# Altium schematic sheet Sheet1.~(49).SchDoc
size A1; SheetNumber: 1; SheetTotal: 1
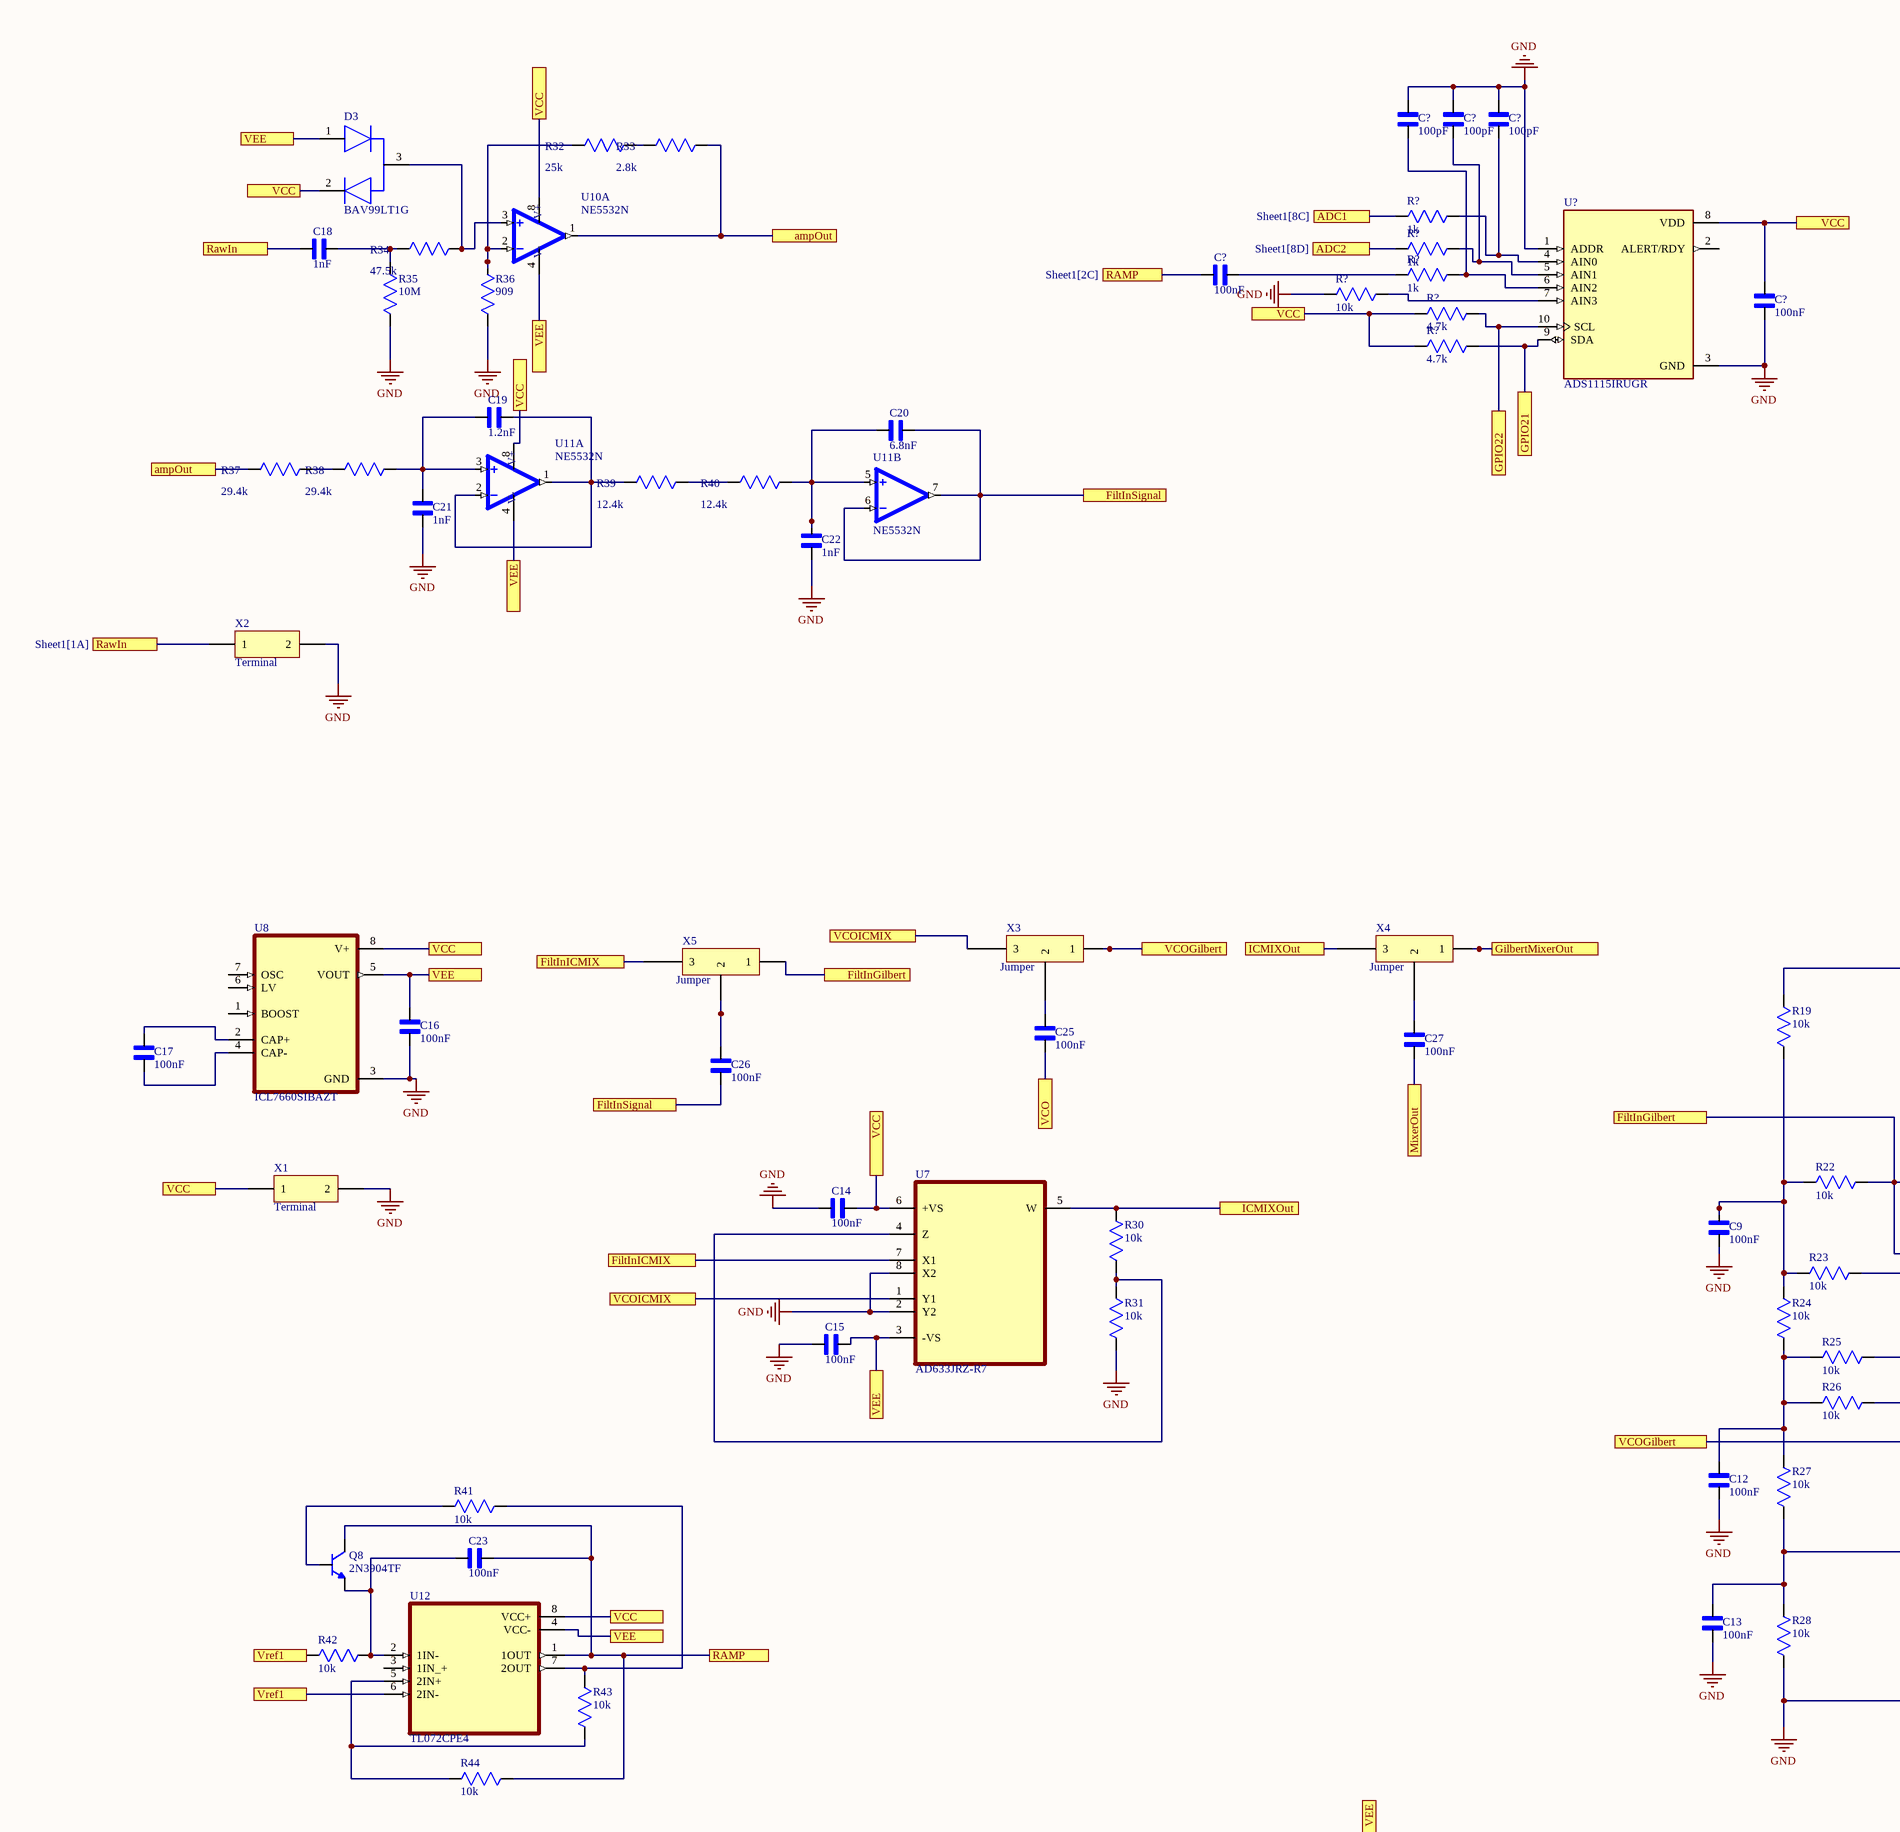
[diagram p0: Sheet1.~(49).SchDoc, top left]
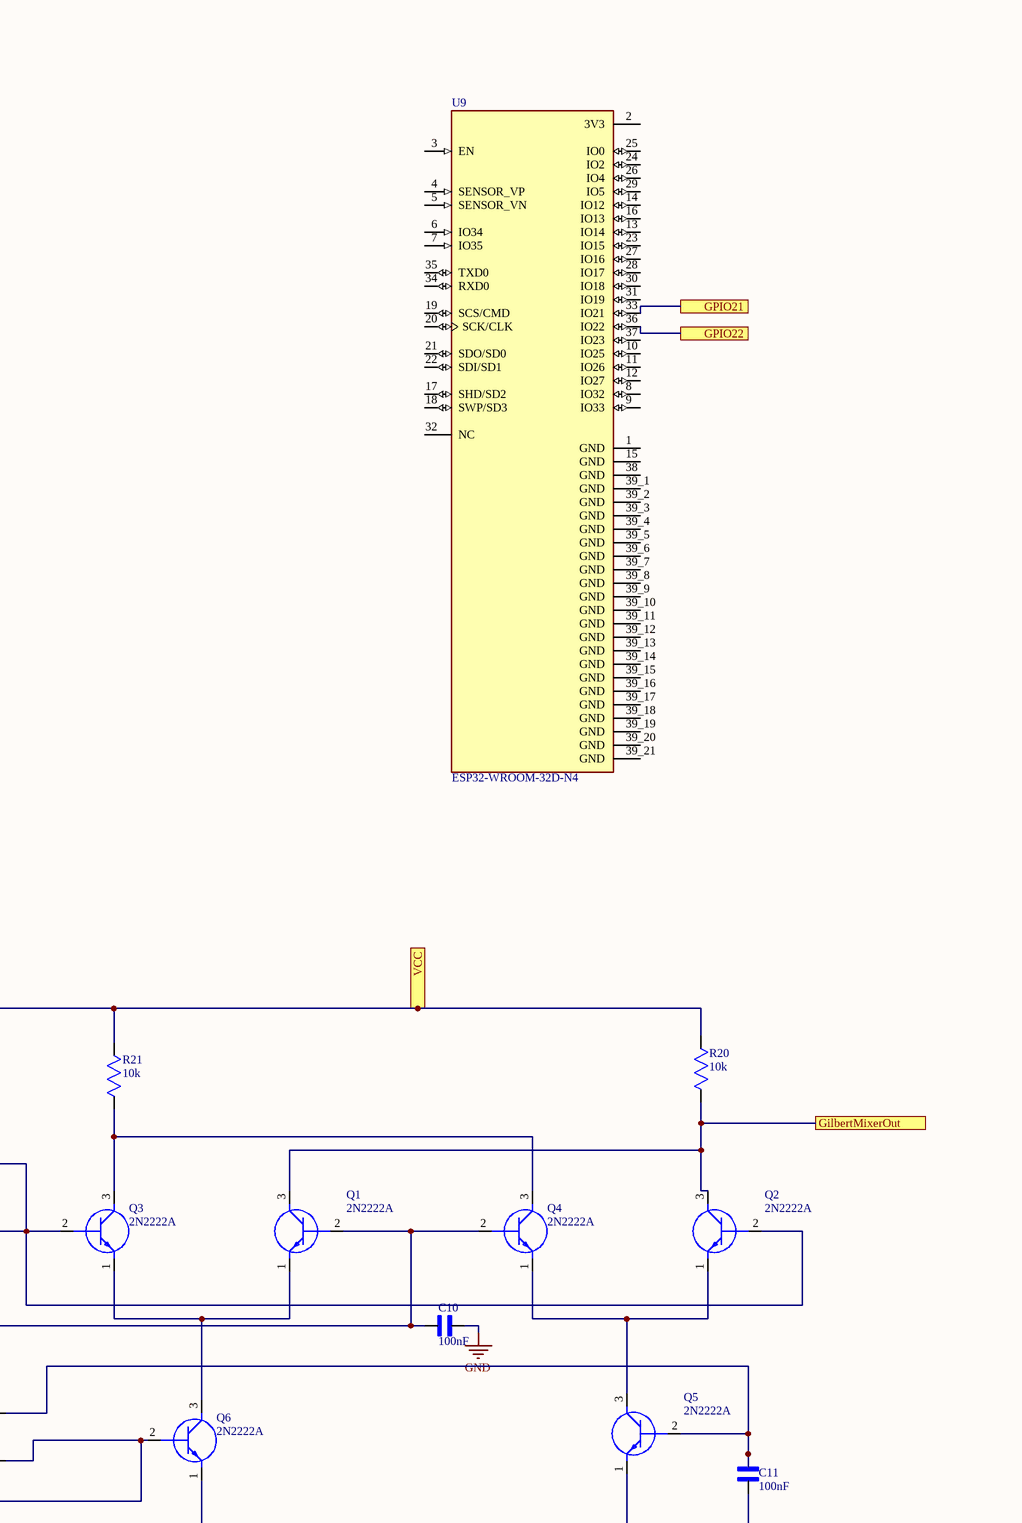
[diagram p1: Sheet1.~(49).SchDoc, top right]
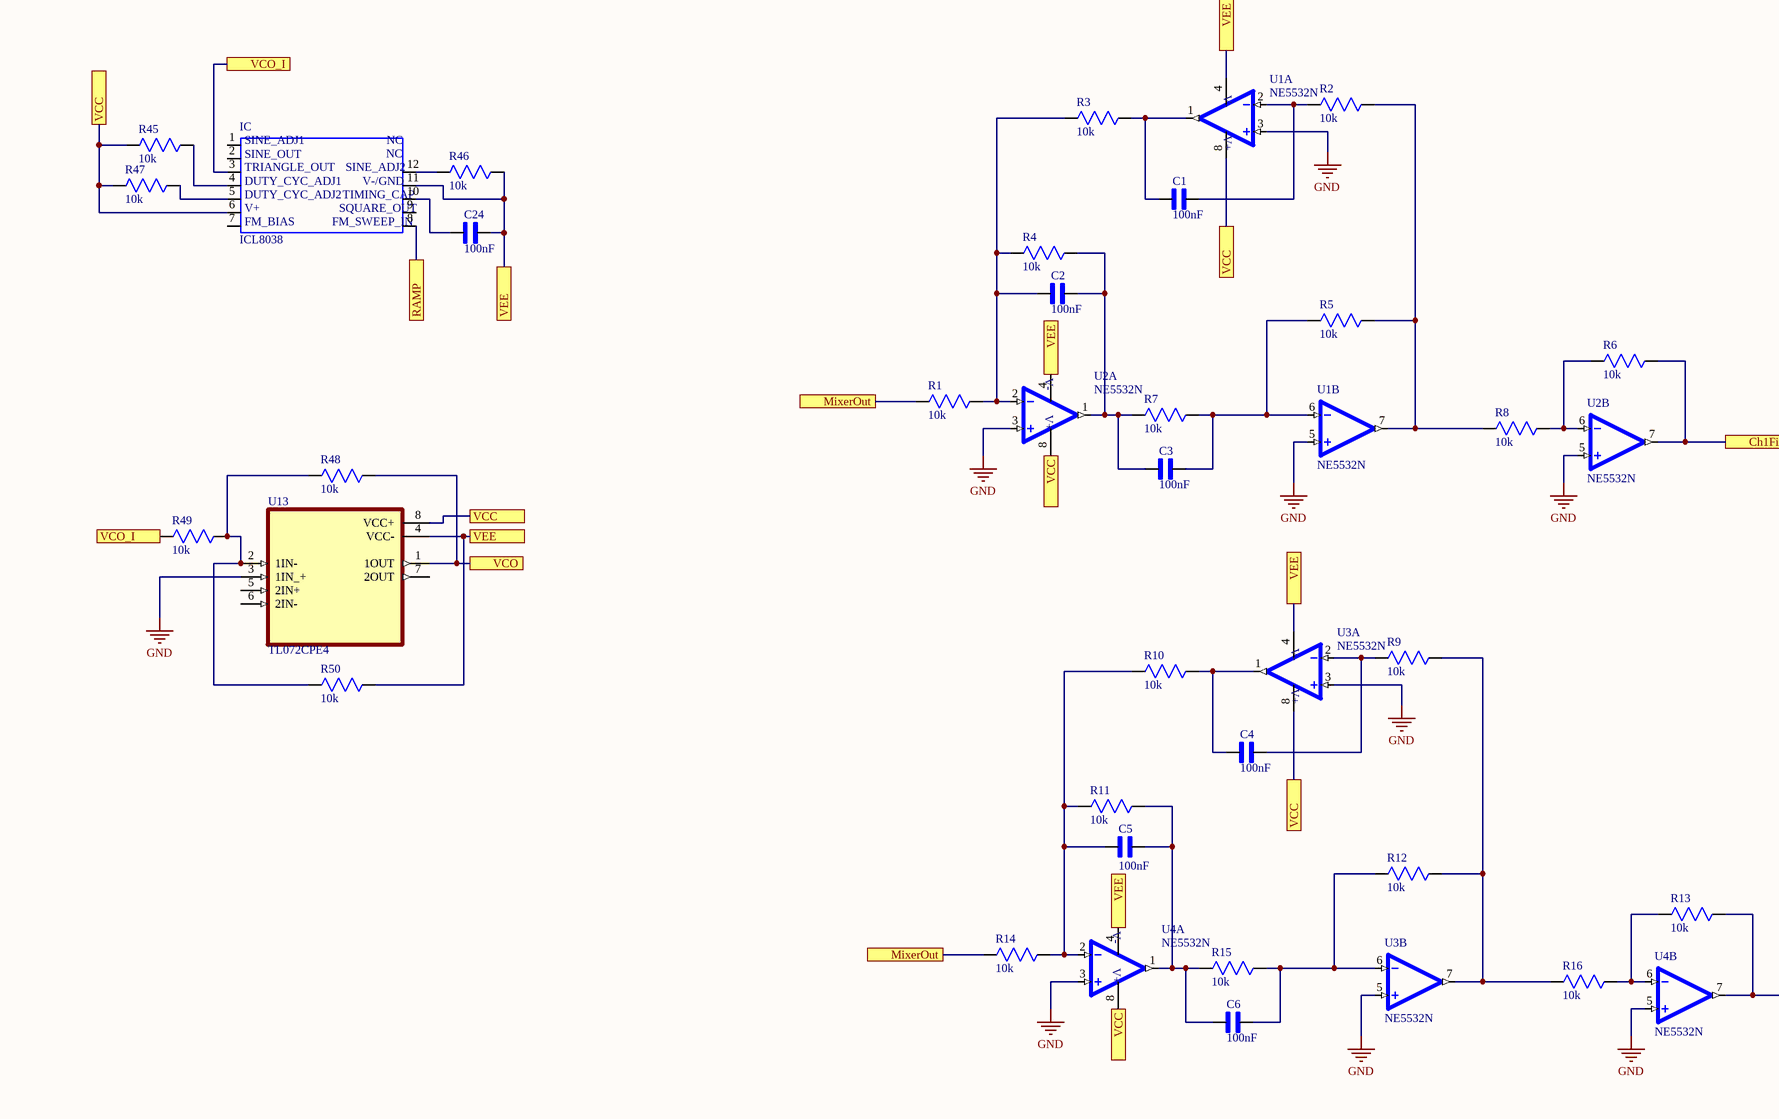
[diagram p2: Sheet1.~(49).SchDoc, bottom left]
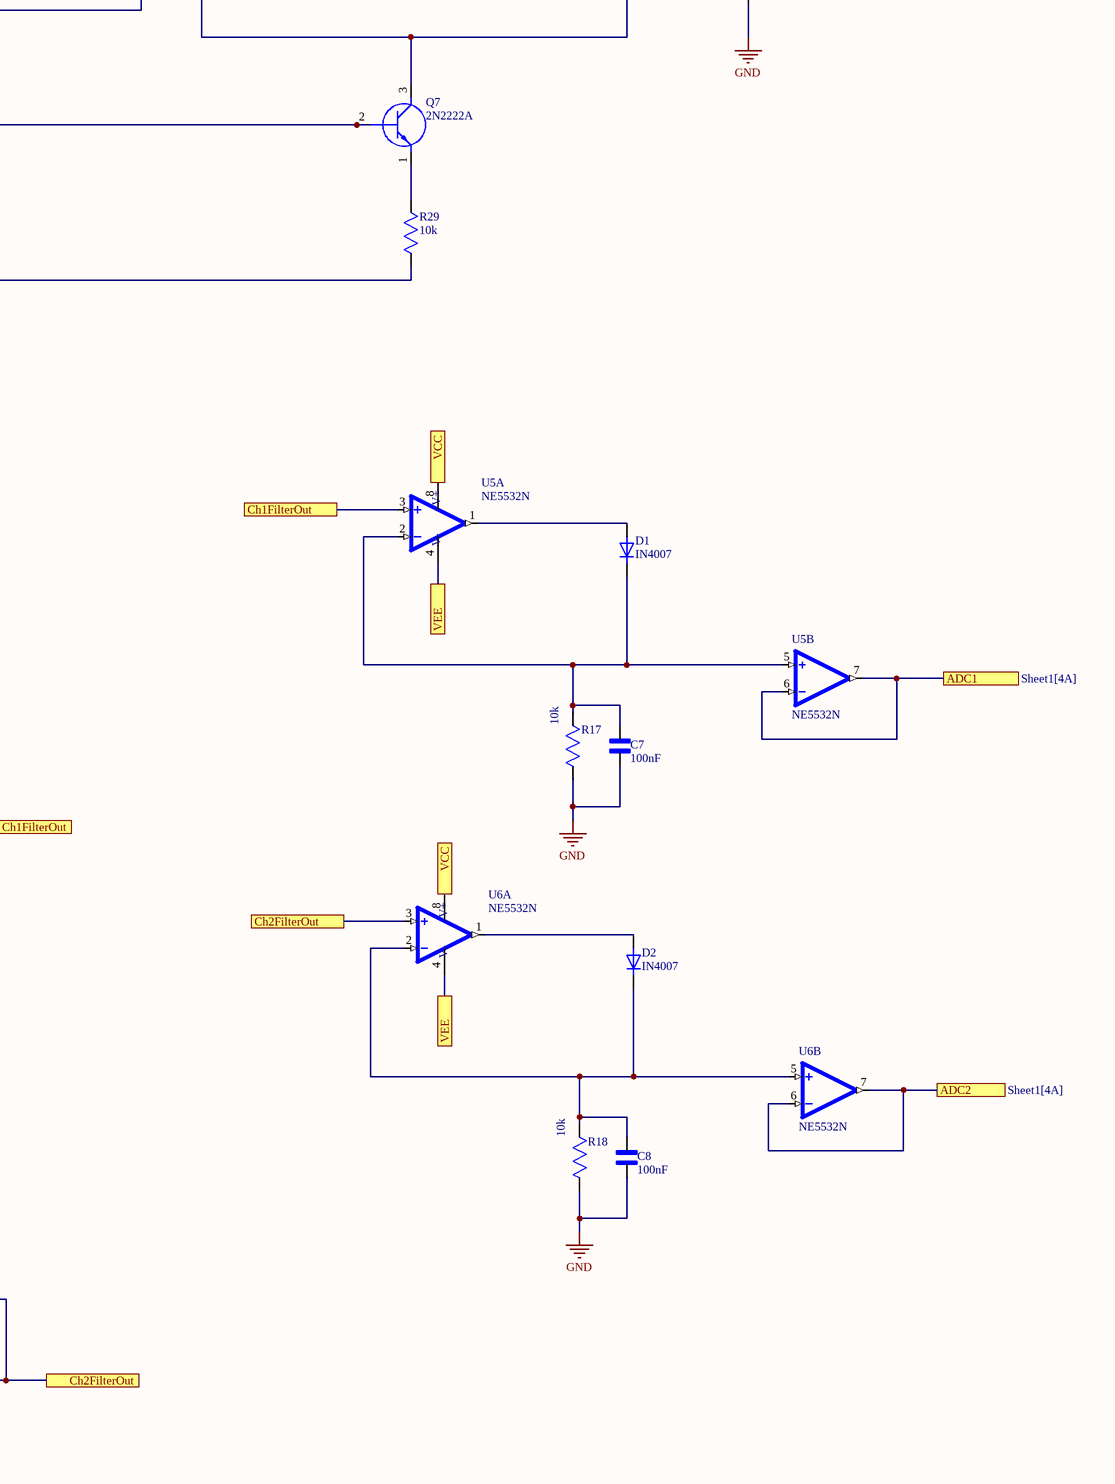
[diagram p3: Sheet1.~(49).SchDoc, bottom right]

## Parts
(Parts that share a designator on the sheet are numbered #1, #2 ... from top to bottom, then left to right.)
C1  100nF  [CAPC2012X95N]
C2  100nF  [CAPC2012X95N]
C3  100nF  [CAPC2012X95N]
C4  100nF  [CAPC2012X95N]
C5  100nF  [CAPC2012X95N]
C6  100nF  [CAPC2012X95N]
C7  100nF  [CAPC2012X95N]
C8  100nF  [CAPC2012X95N]
C9  100nF  [CAPC2012X95N]
C10  100nF  [CAPC2012X95N]
C11  100nF  [CAPC2012X95N]
C12  100nF  [CAPC2012X95N]
C13  100nF  [CAPC2012X95N]
C14  100nF  [CAPC2012X95N]
C15  100nF  [CAPC2012X95N]
C16  100nF  [CAPC2012X95N]
C17  100nF  [CAPC2012X95N]
C18  1nF  [CAPC2012X95N]
C19  1.2nF  [CAPC2012X95N]
C20  6.8nF  [CAPC2012X95N]
C21  1nF  [CAPC2012X95N]
C22  1nF  [CAPC2012X95N]
C23  100nF  [CAPC2012X95N]
C24  100nF  [CAPC2012X95N]
C25  100nF  [CAPC2012X95N]
C26  100nF  [CAPC2012X95N]
C27  100nF  [CAPC2012X95N]
C?#1  100pF  [CAPC2012X95N]
C?#2  100pF  [CAPC2012X95N]
C?#3  100pF  [CAPC2012X95N]
C?#4  100nF  [CAPC2012X95N]
C?#5  100nF  [CAPC2012X95N]
D1  IN4007  [DIOAD1070W78L470D235P]
D2  IN4007  [DIOAD1070W78L470D235P]
D3  BAV99LT1G  [FP-318-08-IPC_B]
IC  ICL8038  [ICL8038]
Q1  2N2222A  [2N2222A]
Q2  2N2222A  [2N2222A]
Q3  2N2222A  [2N2222A]
Q4  2N2222A  [2N2222A]
Q5  2N2222A  [2N2222A]
Q6  2N2222A  [2N2222A]
Q7  2N2222A  [2N2222A]
Q8  2N3904TF  [TO92254P520H877-3]
R1  10k  [RC0805N_YAG-M]
R2  10k  [RC0805N_YAG-M]
R3  10k  [RC0805N_YAG-M]
R4  10k  [RC0805N_YAG-M]
R5  10k  [RC0805N_YAG-M]
R6  10k  [RC0805N_YAG-M]
R7  10k  [RC0805N_YAG-M]
R8  10k  [RC0805N_YAG-M]
R9  10k  [RC0805N_YAG-M]
R10  10k  [RC0805N_YAG-M]
R11  10k  [RC0805N_YAG-M]
R12  10k  [RC0805N_YAG-M]
R13  10k  [RC0805N_YAG-M]
R14  10k  [RC0805N_YAG-M]
R15  10k  [RC0805N_YAG-M]
R16  10k  [RC0805N_YAG-M]
R17  10k  [RC0805N_YAG-M]
R18  10k  [RC0805N_YAG-M]
R19  10k  [RC0805N_YAG-M]
R20  10k  [RC0805N_YAG-M]
R21  10k  [RC0805N_YAG-M]
R22  10k  [RC0805N_YAG-M]
R23  10k  [RC0805N_YAG-M]
R24  10k  [RC0805N_YAG-M]
R25  10k  [RC0805N_YAG-M]
R26  10k  [RC0805N_YAG-M]
R27  10k  [RC0805N_YAG-M]
R28  10k  [RC0805N_YAG-M]
R29  10k  [RC0805N_YAG-M]
R30  10k  [RC0805N_YAG-M]
R31  10k  [RC0805N_YAG-M]
R32  25k  [RC0805N_YAG-M]
R33  2.8k  [RC0805N_YAG-M]
R34  47.5k  [RC0805N_YAG-M]
R35  10M  [RC0805N_YAG-M]
R36  909  [RC0805N_YAG-M]
R37  29.4k  [RC0805N_YAG-M]
R38  29.4k  [RC0805N_YAG-M]
R39  12.4k  [RC0805N_YAG-M]
R40  12.4k  [RC0805N_YAG-M]
R41  10k  [RC0805N_YAG-M]
R42  10k  [RC0805N_YAG-M]
R43  10k  [RC0805N_YAG-M]
R44  10k  [RC0805N_YAG-M]
R45  10k  [RC0805N_YAG-M]
R46  10k  [RC0805N_YAG-M]
R47  10k  [RC0805N_YAG-M]
R48  10k  [RC0805N_YAG-M]
R49  10k  [RC0805N_YAG-M]
R50  10k  [RC0805N_YAG-M]
R?#1  1k  [RC0805N_YAG-M]
R?#2  1k  [RC0805N_YAG-M]
R?#3  1k  [RC0805N_YAG-M]
R?#4  10k  [RC0805N_YAG-M]
R?#5  4.7k  [RC0805N_YAG-M]
R?#6  4.7k  [RC0805N_YAG-M]
U1  NE5532N  [DIP766W45P254L1016H533Q8]  (parts A,B of 2)
U2  NE5532N  [DIP766W45P254L1016H533Q8]  (parts A,B of 2)
U3  NE5532N  [DIP766W45P254L1016H533Q8]  (parts A,B of 2)
U4  NE5532N  [DIP766W45P254L1016H533Q8]  (parts A,B of 2)
U5  NE5532N  [DIP766W45P254L1016H533Q8]  (parts A,B of 2)
U6  NE5532N  [DIP766W45P254L1016H533Q8]  (parts A,B of 2)
U7  AD633JRZ-R7  [SOIC127P600X175-8N]
U8  ICL7660SIBAZT  [SOIC127P600X175-8N]
U9  ESP32-WROOM-32D-N4  [MODULE_ESP32-WROOM-32D-N4]
U10  NE5532N  [DIP766W45P254L1016H533Q8]  (part A of 2)
U11  NE5532N  [DIP766W45P254L1016H533Q8]  (parts A,B of 2)
U12  TL072CPE4  [DIP794W45P254L959H508Q8]
U13  TL072CPE4  [DIP794W45P254L959H508Q8]
U?  ADS1115IRUGR  [IC_ADS1115IRUGR]
X1  Terminal  [CON_TERMINAL_2POL]
X2  Terminal  [CON_TERMINAL_2POL]
X3  Jumper  [CON_JUMPER_3POL]
X4  Jumper  [CON_JUMPER_3POL]
X5  Jumper  [CON_JUMPER_3POL]

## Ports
ADC1 (see Sheet1[4A]), ADC1 (see Sheet1[8C]), ADC2 (see Sheet1[4A]), ADC2 (see Sheet1[8D]), ampOut (see Sheet1[1A]), ampOut (see Sheet1[3A]), Ch1FilterOut (see Sheet1[6D]), Ch1FilterOut (see Sheet1[7C]), Ch2FilterOut (see Sheet1[6D]), Ch2FilterOut (see Sheet1[7D]), FiltInGilbert (see Sheet1[3B]), FiltInGilbert (see Sheet1[5B]), FiltInICMIX (see Sheet1[2B]), FiltInSignal (see Sheet1[2B]), FiltInSignal (see Sheet1[4A]), GilbertMixerOut (see Sheet1[5B]), GilbertMixerOut (see Sheet1[8B]), GPIO21 (see Sheet1[5A]), GPIO21 (see Sheet1[8A]), GPIO22 (see Sheet1[5A]), GPIO22 (see Sheet1[8A]), ICMIXOut (see Sheet1[4B]), MixerOut (see Sheet1[3D]), MixerOut (see Sheet1[3D], Sheet1[4B]), RAMP (see Sheet1[2C]), RAMP (see Sheet1[2C], Sheet1[4A]), RawIn (see Sheet1[1A]), VCC (see Sheet1[1A], Sheet1[1B], Sheet1[1C], Sheet1[2A], Sheet1[2B], Sheet1[2C], Sheet1[2D], Sheet1[3B], Sheet1[4A], Sheet1[4C], Sheet1[4D], Sheet1[5D], Sheet1[6A], Sheet1[7B], Sheet1[7C]), VCC (see Sheet1[1A], Sheet1[1B], Sheet1[1C], Sheet1[2A], Sheet1[2B], Sheet1[2C], Sheet1[2D], Sheet1[3B], Sheet1[4A], Sheet1[4C], Sheet1[4D], Sheet1[5D], Sheet1[6A], Sheet1[7B], Sheet1[7C], Sheet1[7D]), VCC (see Sheet1[1A], Sheet1[1B], Sheet1[1C], Sheet1[2A], Sheet1[2B], Sheet1[2C], Sheet1[2D], Sheet1[3B], Sheet1[4A], Sheet1[4C], Sheet1[4D], Sheet1[5D], Sheet1[6A], Sheet1[7B], Sheet1[7D]), VCC (see Sheet1[1A], Sheet1[1B], Sheet1[1C], Sheet1[2A], Sheet1[2B], Sheet1[2C], Sheet1[2D], Sheet1[3B], Sheet1[4A], Sheet1[4C], Sheet1[4D], Sheet1[5D], Sheet1[6A], Sheet1[7C], Sheet1[7D]), VCC (see Sheet1[1A], Sheet1[1B], Sheet1[1C], Sheet1[2A], Sheet1[2B], Sheet1[2C], Sheet1[2D], Sheet1[3B], Sheet1[4A], Sheet1[4C], Sheet1[4D], Sheet1[5D], Sheet1[7B], Sheet1[7C], Sheet1[7D]), VCC (see Sheet1[1A], Sheet1[1B], Sheet1[1C], Sheet1[2A], Sheet1[2B], Sheet1[2C], Sheet1[2D], Sheet1[3B], Sheet1[4A], Sheet1[4C], Sheet1[4D], Sheet1[6A], Sheet1[7B], Sheet1[7C], Sheet1[7D]), VCC (see Sheet1[1A], Sheet1[1B], Sheet1[1C], Sheet1[2A], Sheet1[2B], Sheet1[2C], Sheet1[2D], Sheet1[3B], Sheet1[4A], Sheet1[4D], Sheet1[5D], Sheet1[6A], Sheet1[7B], Sheet1[7C], Sheet1[7D]), VCC (see Sheet1[1A], Sheet1[1B], Sheet1[1C], Sheet1[2A], Sheet1[2B], Sheet1[2C], Sheet1[2D], Sheet1[3B], Sheet1[4C], Sheet1[4D], Sheet1[5D], Sheet1[6A], Sheet1[7B], Sheet1[7C], Sheet1[7D]), VCC (see Sheet1[1A], Sheet1[1B], Sheet1[1C], Sheet1[2A], Sheet1[2B], Sheet1[2C], Sheet1[2D], Sheet1[4A], Sheet1[4C], Sheet1[4D], Sheet1[5D], Sheet1[6A], Sheet1[7B], Sheet1[7C], Sheet1[7D]), VCC (see Sheet1[1A], Sheet1[1B], Sheet1[1C], Sheet1[2A], Sheet1[2B], Sheet1[2C], Sheet1[3B], Sheet1[4A], Sheet1[4C], Sheet1[4D], Sheet1[5D], Sheet1[6A], Sheet1[7B], Sheet1[7C], Sheet1[7D]), VCC (see Sheet1[1A], Sheet1[1B], Sheet1[1C], Sheet1[2A], Sheet1[2B], Sheet1[2D], Sheet1[3B], Sheet1[4A], Sheet1[4C], Sheet1[4D], Sheet1[5D], Sheet1[6A], Sheet1[7B], Sheet1[7C], Sheet1[7D]), VCC (see Sheet1[1A], Sheet1[1B], Sheet1[1C], Sheet1[2A], Sheet1[2C], Sheet1[2D], Sheet1[3B], Sheet1[4A], Sheet1[4C], Sheet1[4D], Sheet1[5D], Sheet1[6A], Sheet1[7B], Sheet1[7C], Sheet1[7D]), VCC (see Sheet1[1A], Sheet1[1B], Sheet1[2A], Sheet1[2B], Sheet1[2C], Sheet1[2D], Sheet1[3B], Sheet1[4A], Sheet1[4C], Sheet1[4D], Sheet1[5D], Sheet1[6A], Sheet1[7B], Sheet1[7C], Sheet1[7D]), VCC (see Sheet1[1A], Sheet1[1C], Sheet1[2A], Sheet1[2B], Sheet1[2C], Sheet1[2D], Sheet1[3B], Sheet1[4A], Sheet1[4C], Sheet1[4D], Sheet1[5D], Sheet1[6A], Sheet1[7B], Sheet1[7C], Sheet1[7D]), VCC (see Sheet1[1B], Sheet1[1C], Sheet1[2A], Sheet1[2B], Sheet1[2C], Sheet1[2D], Sheet1[3B], Sheet1[4A], Sheet1[4C], Sheet1[4D], Sheet1[5D], Sheet1[6A], Sheet1[7B], Sheet1[7C], Sheet1[7D]), VCO (see Sheet1[2D]), VCO (see Sheet1[3B]), VCO_I (see Sheet1[1D]), VCO_I (see Sheet1[2C]), VCOGilbert (see Sheet1[4B]), VCOGilbert (see Sheet1[5B]), VCOICMIX (see Sheet1[2B]), VCOICMIX (see Sheet1[3B]), VEE (see Sheet1[1A], Sheet1[2A], Sheet1[2B], Sheet1[2C], Sheet1[2D], Sheet1[3B], Sheet1[4C], Sheet1[4D], Sheet1[5D], Sheet1[7C]), VEE (see Sheet1[1A], Sheet1[2A], Sheet1[2B], Sheet1[2C], Sheet1[2D], Sheet1[3B], Sheet1[4C], Sheet1[4D], Sheet1[5D], Sheet1[7C], Sheet1[7D]), VEE (see Sheet1[1A], Sheet1[2A], Sheet1[2B], Sheet1[2C], Sheet1[2D], Sheet1[3B], Sheet1[4C], Sheet1[4D], Sheet1[5D], Sheet1[7D]), VEE (see Sheet1[1A], Sheet1[2A], Sheet1[2B], Sheet1[2C], Sheet1[2D], Sheet1[3B], Sheet1[4C], Sheet1[4D], Sheet1[7C], Sheet1[7D]), VEE (see Sheet1[1A], Sheet1[2A], Sheet1[2B], Sheet1[2C], Sheet1[2D], Sheet1[3B], Sheet1[4C], Sheet1[5D], Sheet1[7C], Sheet1[7D]), VEE (see Sheet1[1A], Sheet1[2A], Sheet1[2B], Sheet1[2C], Sheet1[2D], Sheet1[4C], Sheet1[4D], Sheet1[5D], Sheet1[7C], Sheet1[7D]), VEE (see Sheet1[1A], Sheet1[2A], Sheet1[2B], Sheet1[2C], Sheet1[3B], Sheet1[4C], Sheet1[4D], Sheet1[5D], Sheet1[7C], Sheet1[7D]), VEE (see Sheet1[1A], Sheet1[2A], Sheet1[2C], Sheet1[2D], Sheet1[3B], Sheet1[4C], Sheet1[4D], Sheet1[5D], Sheet1[7C], Sheet1[7D]), VEE (see Sheet1[2A], Sheet1[2B], Sheet1[2C], Sheet1[2D], Sheet1[3B], Sheet1[4C], Sheet1[4D], Sheet1[5D], Sheet1[7C], Sheet1[7D]), Vref1 (see Sheet1[1C])

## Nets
GND: C7.2 C8.2 C9.2 C10.1 C11.1 C12.2 C13.2 C14.1 C15.1 C16.2 C21.1 C22.1 C?#1.2 C?#2.2 C?#3.2 C?#5.1 R17.1 R18.1 R28.1 R29.1 R31.2 R35.2 R36.2 R?#4.2 U1.3(+INA) U1.5(+INB) U2.3(+INA) U2.5(+INB) U3.3(+INA) U3.5(+INB) U4.3(+INA) U4.5(+INB) U7.2(Y2) U7.8(X2) U8.3(GND) U13.3(1IN_+) U?.1(ADDR) U?.3(GND) X1.2 X2.2
ADC1: R?#1.2 U5.6(-INB) U5.7(OUTB) ; port ADC1
ADC2: R?#2.2 U6.6(-INB) U6.7(OUTB) ; port ADC2
ampOut: R33.1 R37.2 U10.1(OUTA) ; port ampOut
Ch1FilterOut: R6.1 U2.7(OUTB) U5.3(+INA) ; port Ch1FilterOut
Ch2FilterOut: R13.1 U4.7(OUTB) U6.3(+INA) ; port Ch2FilterOut
FiltInGilbert: Q2.2(B) Q3.2(B) R22.2 X5.1 ; port FiltInGilbert
FiltInICMIX: U7.7(X1) X5.3 ; port FiltInICMIX
FiltInSignal: C20.2 C26.2 U11.6(-INB) U11.7(OUTB) ; port FiltInSignal
GilbertMixerOut: Q1.3(C) Q2.3(C) R20.1 X4.1 ; port GilbertMixerOut
GPIO21: R?#6.1 U9.33(IO21) U?.9(SDA) ; port GPIO21
GPIO22: R?#5.1 U9.36(IO22) U?.10(SCL) ; port GPIO22
ICMIXOut: R30.1 U7.5(W) X4.3 ; port ICMIXOut
MixerOut: C27.2 R1.2 R14.2 ; port MixerOut
RAMP: C23.2 C?#4.1 IC.8 Q8.3(C) R44.1 U12.1(1OUT) ; port RAMP
RawIn: C18.2 X2.1 ; port RawIn
VCC: C14.2 C?#5.2 D3.2(C) IC.6 R19.2 R20.2 R21.2 R45.2 R47.2 R?#5.2 R?#6.2 U1.8(V+) U2.8(V+) U3.8(V+) U4.8(V+) U5.8(V+) U6.8(V+) U7.6(+VS) U8.8(V+) U10.8(V+) U11.8(V+) U12.8(VCC+) U13.8(VCC+) U?.8(VDD) X1.1 ; port VCC
VCO: C25.2 R48.1 U13.1(1OUT) ; port VCO
VCO_I: IC.3 R49.2 ; port VCO_I
VCOGilbert: Q6.2(B) R26.2 X3.1 ; port VCOGilbert
VCOICMIX: U7.1(Y1) X3.3 ; port VCOICMIX
VEE: C15.2 C16.1 C24.2 D3.1(A) IC.11 R46.1 R50.1 U1.4(V-) U2.4(V-) U3.4(V-) U4.4(V-) U5.4(V-) U6.4(V-) U7.3(-VS) U8.5(VOUT) U10.4(V-) U11.4(V-) U12.4(VCC-) U13.4(VCC-) ; port VEE
Vref1: R42.2 U12.6(2IN-) ; port Vref1
NetC1_1: C1.1 R3.1 U1.1(OUTA)
NetC1_2: C1.2 R2.2 U1.2(-INA)
NetC2_1: C2.1 R1.1 R3.2 R4.2 U2.2(-INA)
NetC2_2: C2.2 C3.1 R4.1 R7.2 U2.1(OUTA)
NetC3_2: C3.2 R5.2 R7.1 U1.6(-INB)
NetC4_1: C4.1 R10.1 U3.1(OUTA)
NetC4_2: C4.2 R9.2 U3.2(-INA)
NetC5_1: C5.1 R10.2 R11.2 R14.1 U4.2(-INA)
NetC5_2: C5.2 C6.1 R11.1 R15.2 U4.1(OUTA)
NetC6_2: C6.2 R12.2 R15.1 U3.6(-INB)
NetC7_1: C7.1 D1.C R17.2 U5.2(-INA) U5.5(+INB)
NetC8_1: C8.1 D2.C R18.2 U6.2(-INA) U6.5(+INB)
NetC9_1: C9.1 R19.1 R22.1 R23.1 R24.2
NetC10_2: C10.2 Q1.2(B) Q4.2(B) R23.2
NetC11_2: C11.2 Q5.2(B) R25.2
NetC12_1: C12.1 R24.1 R25.1 R26.1 R27.2
NetC13_1: C13.1 Q7.2(B) R27.1 R28.2
NetC17_1: C17.1 U8.2(CAP+)
NetC17_2: C17.2 U8.4(CAP-)
NetC18_1: C18.1 R34.2 R35.1
NetC19_1: C19.1 C21.2 R38.1 U11.3(+INA)
NetC19_2: C19.2 R39.2 U11.1(OUTA) U11.2(-INA)
NetC20_1: C20.1 C22.2 R40.1 U11.5(+INB)
NetC23_1: C23.1 Q8.1(E) R42.1 U12.2(1IN-)
NetC24_1: C24.1 IC.10
NetC25_1: C25.1 X3.2
NetC26_1: C26.1 X5.2
NetC27_1: C27.1 X4.2
NetC?#1_1: C?#1.1 R?#3.1 U?.6(AIN2)
NetC?#2_1: C?#2.1 R?#2.1 U?.5(AIN1)
NetC?#3_1: C?#3.1 R?#1.1 U?.4(AIN0)
NetC?#4_2: C?#4.2 R?#3.2
NetD1_A: D1.A U5.1(OUTA)
NetD2_A: D2.A U6.1(OUTA)
NetD3_3: D3.3(CATHODE/ANODE) R34.1 U10.3(+INA)
NetIC_4: IC.4 R45.1
NetIC_5: IC.5 R47.1
NetIC_12: IC.12 R46.2
NetQ1_1: Q1.1(E) Q3.1(E) Q6.3(C)
NetQ2_1: Q2.1(E) Q4.1(E) Q5.3(C)
NetQ3_3: Q3.3(C) Q4.3(C) R21.1
NetQ5_1: Q5.1(E) Q6.1(E) Q7.3(C)
NetQ7_1: Q7.1(E) R29.2
NetQ8_2: Q8.2(B) R41.2
NetR2_1: R2.1 R5.1 R8.2 U1.7(OUTB)
NetR6_2: R6.2 R8.1 U2.6(-INB)
NetR9_1: R9.1 R12.1 R16.2 U3.7(OUTB)
NetR13_2: R13.2 R16.1 U4.6(-INB)
NetR30_2: R30.2 R31.1 U7.4(Z)
NetR32_1: R32.1 R33.2
NetR32_2: R32.2 R36.1 U10.2(-INA)
NetR37_1: R37.1 R38.2
NetR39_1: R39.1 R40.2
NetR41_1: R41.1 R43.1 U12.7(2OUT)
NetR43_2: R43.2 R44.2 U12.5(2IN+)
NetR48_2: R48.2 R49.1 R50.2 U13.2(1IN-)
NetR?#4_1: R?#4.1 U?.7(AIN3)

Not connected (* = marked no-connect by the designer): IC 1 2 7 9; U8 1(BOOST) 6(LV) 7(OSC); U9 1(GND) 2(3V3) 3(EN) 4(SENSOR_VP) 5(SENSOR_VN) 6(IO34) 7(IO35) 8(IO32) 9(IO33) 10(IO25) 11(IO26) 12(IO27) 13(IO14) 14(IO12) 15(GND) 16(IO13) 17(SHD/SD2) 18(SWP/SD3) 19(SCS/CMD) 20(SCK/CLK) 21(SDO/SD0) 22(SDI/SD1) 23(IO15) 24(IO2) 25(IO0) 26(IO4) 27(IO16) 28(IO17) 29(IO5) 30(IO18) 31(IO19) 32(NC) 34(RXD0) 35(TXD0) 37(IO23) 38(GND) 39_1(GND) 39_2(GND) 39_3(GND) 39_4(GND) 39_5(GND) 39_6(GND) 39_7(GND) 39_8(GND) 39_9(GND) 39_10(GND) 39_11(GND) 39_12(GND) 39_13(GND) 39_14(GND) 39_15(GND) 39_16(GND) 39_17(GND) 39_18(GND) 39_19(GND) 39_20(GND) 39_21(GND); U12 3(1IN_+); U13 5(2IN+) 6(2IN-) 7(2OUT); U? 2(ALERT/RDY)

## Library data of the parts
C1-C27 = CAP_0805_GENERIC: 0.1 ÂµF Â±10% 50V Ceramic Capacitor X7R 0805 (2012 Metric); MF: Samsung Electro-Mechanics; MP: CL21B104KBCNNNC
C?#1-C?#5 = CAP_0805_GENERIC: 0.1 ÂµF Â±10% 50V Ceramic Capacitor X7R 0805 (2012 Metric); Value: 1nF; MF: Samsung Electro-Mechanics; MP: CL21B104KBCNNNC
D1 D2 = IN4007: Diode Standard 1000 V 1A Through Hole DO-204AL (DO-41); MF: Vishay Semiconductor
D3 = CMP-07163-000036-1: DIODE ARRAY 100V 215MA SOT23-3; Capacitance: 1.5pF; Current Rating: 200mA; Max Repetitive Reverse Voltage (Vrrm): 70V; Forward Voltage: 1.25V; Max Forward Surge Current (Ifsm): 500mA; Peak Reverse Current: 2.5uA; Forward Current: 150mA; Peak Non-Repetitive Surge Current: 2A; Reverse Recovery Time: 6ns
IC = ICL8038: IC OSCILL GEN/VOLT CONTROL 14DIP; MF: Renesas Electronics
Q1-Q7 = 2N2222A: Transistor BJT NPN; Manufacturer_Name: Diotec
Q8 = 2N3904TF: Transistor General Purpose BJT NPN 40 Volt 0.2 Amp 3-Pin TO-92 Tape And Reel; MF: Fairchild Semiconductor
R1-R50 R?#4 = RES_0805_GENERIC_1: Description; Manufacturer_Name: Yageo; Manufacturer_Part_Number: RC0805FR-0710KL
R?#1-R?#3 R?#5 R?#6 = RES_0805_GENERIC_1: Description; Manufacturer_Name: Yageo; Manufacturer_Part_Number: RC0805FR-0710KL; Value: 10k
U1-U6 U10 U11 = NE5532N: IC, OP AMP, DUAL; No. of Amplifiers: 2 Amplifier; Bandwidth: 10MHz; Slew Rate: 8V/Âµs; Supply Voltage Range: Â± 15V; Amplifier Case Style: DIP; No. of Pins: 8Pins; Operating Temperature Min: 0Â°C; Operating Temperature Max: 70Â°C; MSL: -; SVHC: No SVHC (1; MF: Fairchild Semiconductor
U7 = AD633JRZ-R7: Analog Multiplier 4-Quadrant 8-SOIC; MF: Analog Devices; MP: AD633AR
U8 = ICL7660SIBAZT: Charge Pump Switching Regulator IC Positive or Negative Fixed -Vin, 2Vin 1 Output 45mA 8-SOIC (0.154, 3.90mm Width); MF: Renesas Electronics America Inc
U9 = ESP32-WROOM-32D-N4: Bluetooth, WiFi 802.11b/g/n, Bluetooth v4.2 +EDR, Class 1, 2 and 3 Transceiver Module 2.4GHz ~ 2.5GHz Integrated, Trace Surface Mount; MF: Espressif Systems
U12 U13 = TL072CPE4: Dual Low-Noise JFET-Input General-Purpose Operational Amplifier 8-PDIP 0 to 70; MF: Texas Instruments
U? = ADS1115IRUGR: 16-bit, 860-SPS, 4-channel, delta-sigma ADC with PGA, oscillator, VREF, comparator and I2C; MF: Texas Instruments
X1 X2 = CON_TERMINAL_2POL: Terminal Screw; Manufacturer_Name: Yageo; Manufacturer_Part_Number: RC0805FR-0710KL; Value: 10k
X3-X5 = CON_JUMPER_3POL: Manufacturer_Name: Yageo; Manufacturer_Part_Number: RC0805FR-0710KL; Value: 10k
